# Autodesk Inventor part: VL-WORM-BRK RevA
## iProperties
Created: 2007-10
Part Number: VL-WORM-BRK RevA
Material: Steel
Document SubType Name: Modeling
Density: 7.85 g/cm^3
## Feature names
1. Base1
2. Extrusion1
3. Extrusion2
4. Split1
